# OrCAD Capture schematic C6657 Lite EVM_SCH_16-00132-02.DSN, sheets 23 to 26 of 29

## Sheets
23 PAGE12 : MMC, HYPERLINK CONN: size C; title: MMC, HYPERLINK & 80 CONN
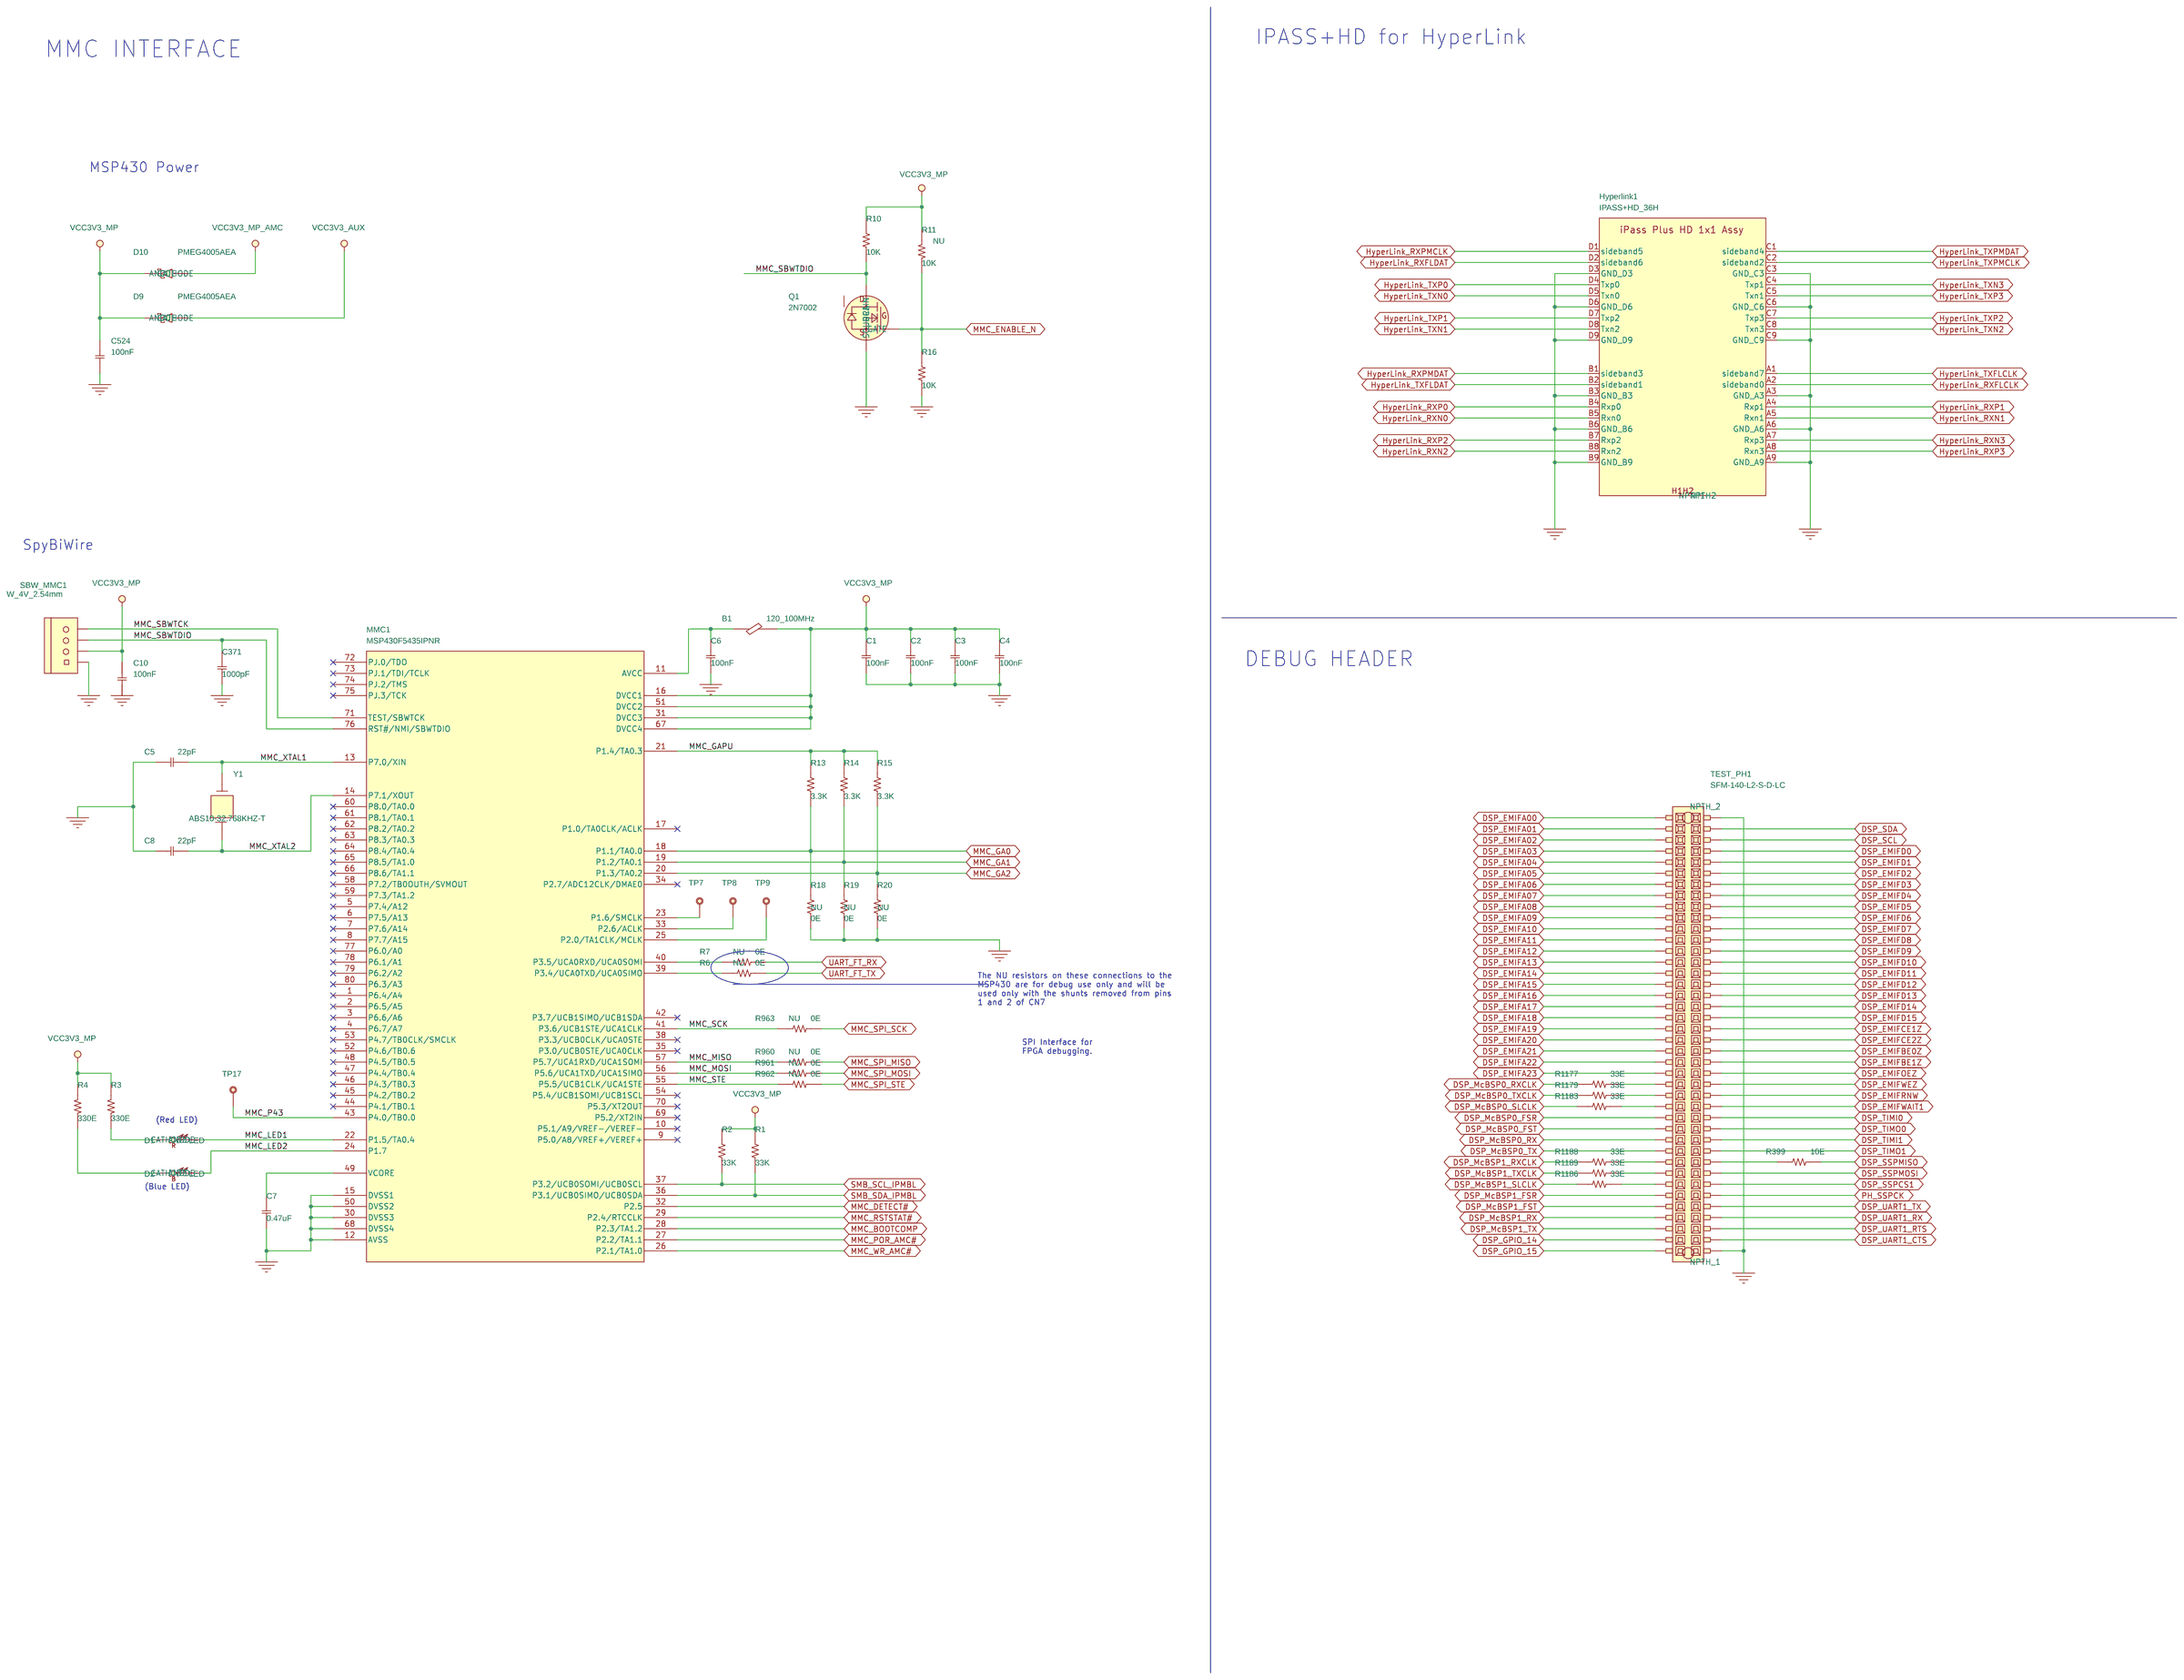
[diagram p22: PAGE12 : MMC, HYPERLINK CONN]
24 PAGE09 : FPGA INTERFACE CTRL: title: CLOCK DIAGRAM
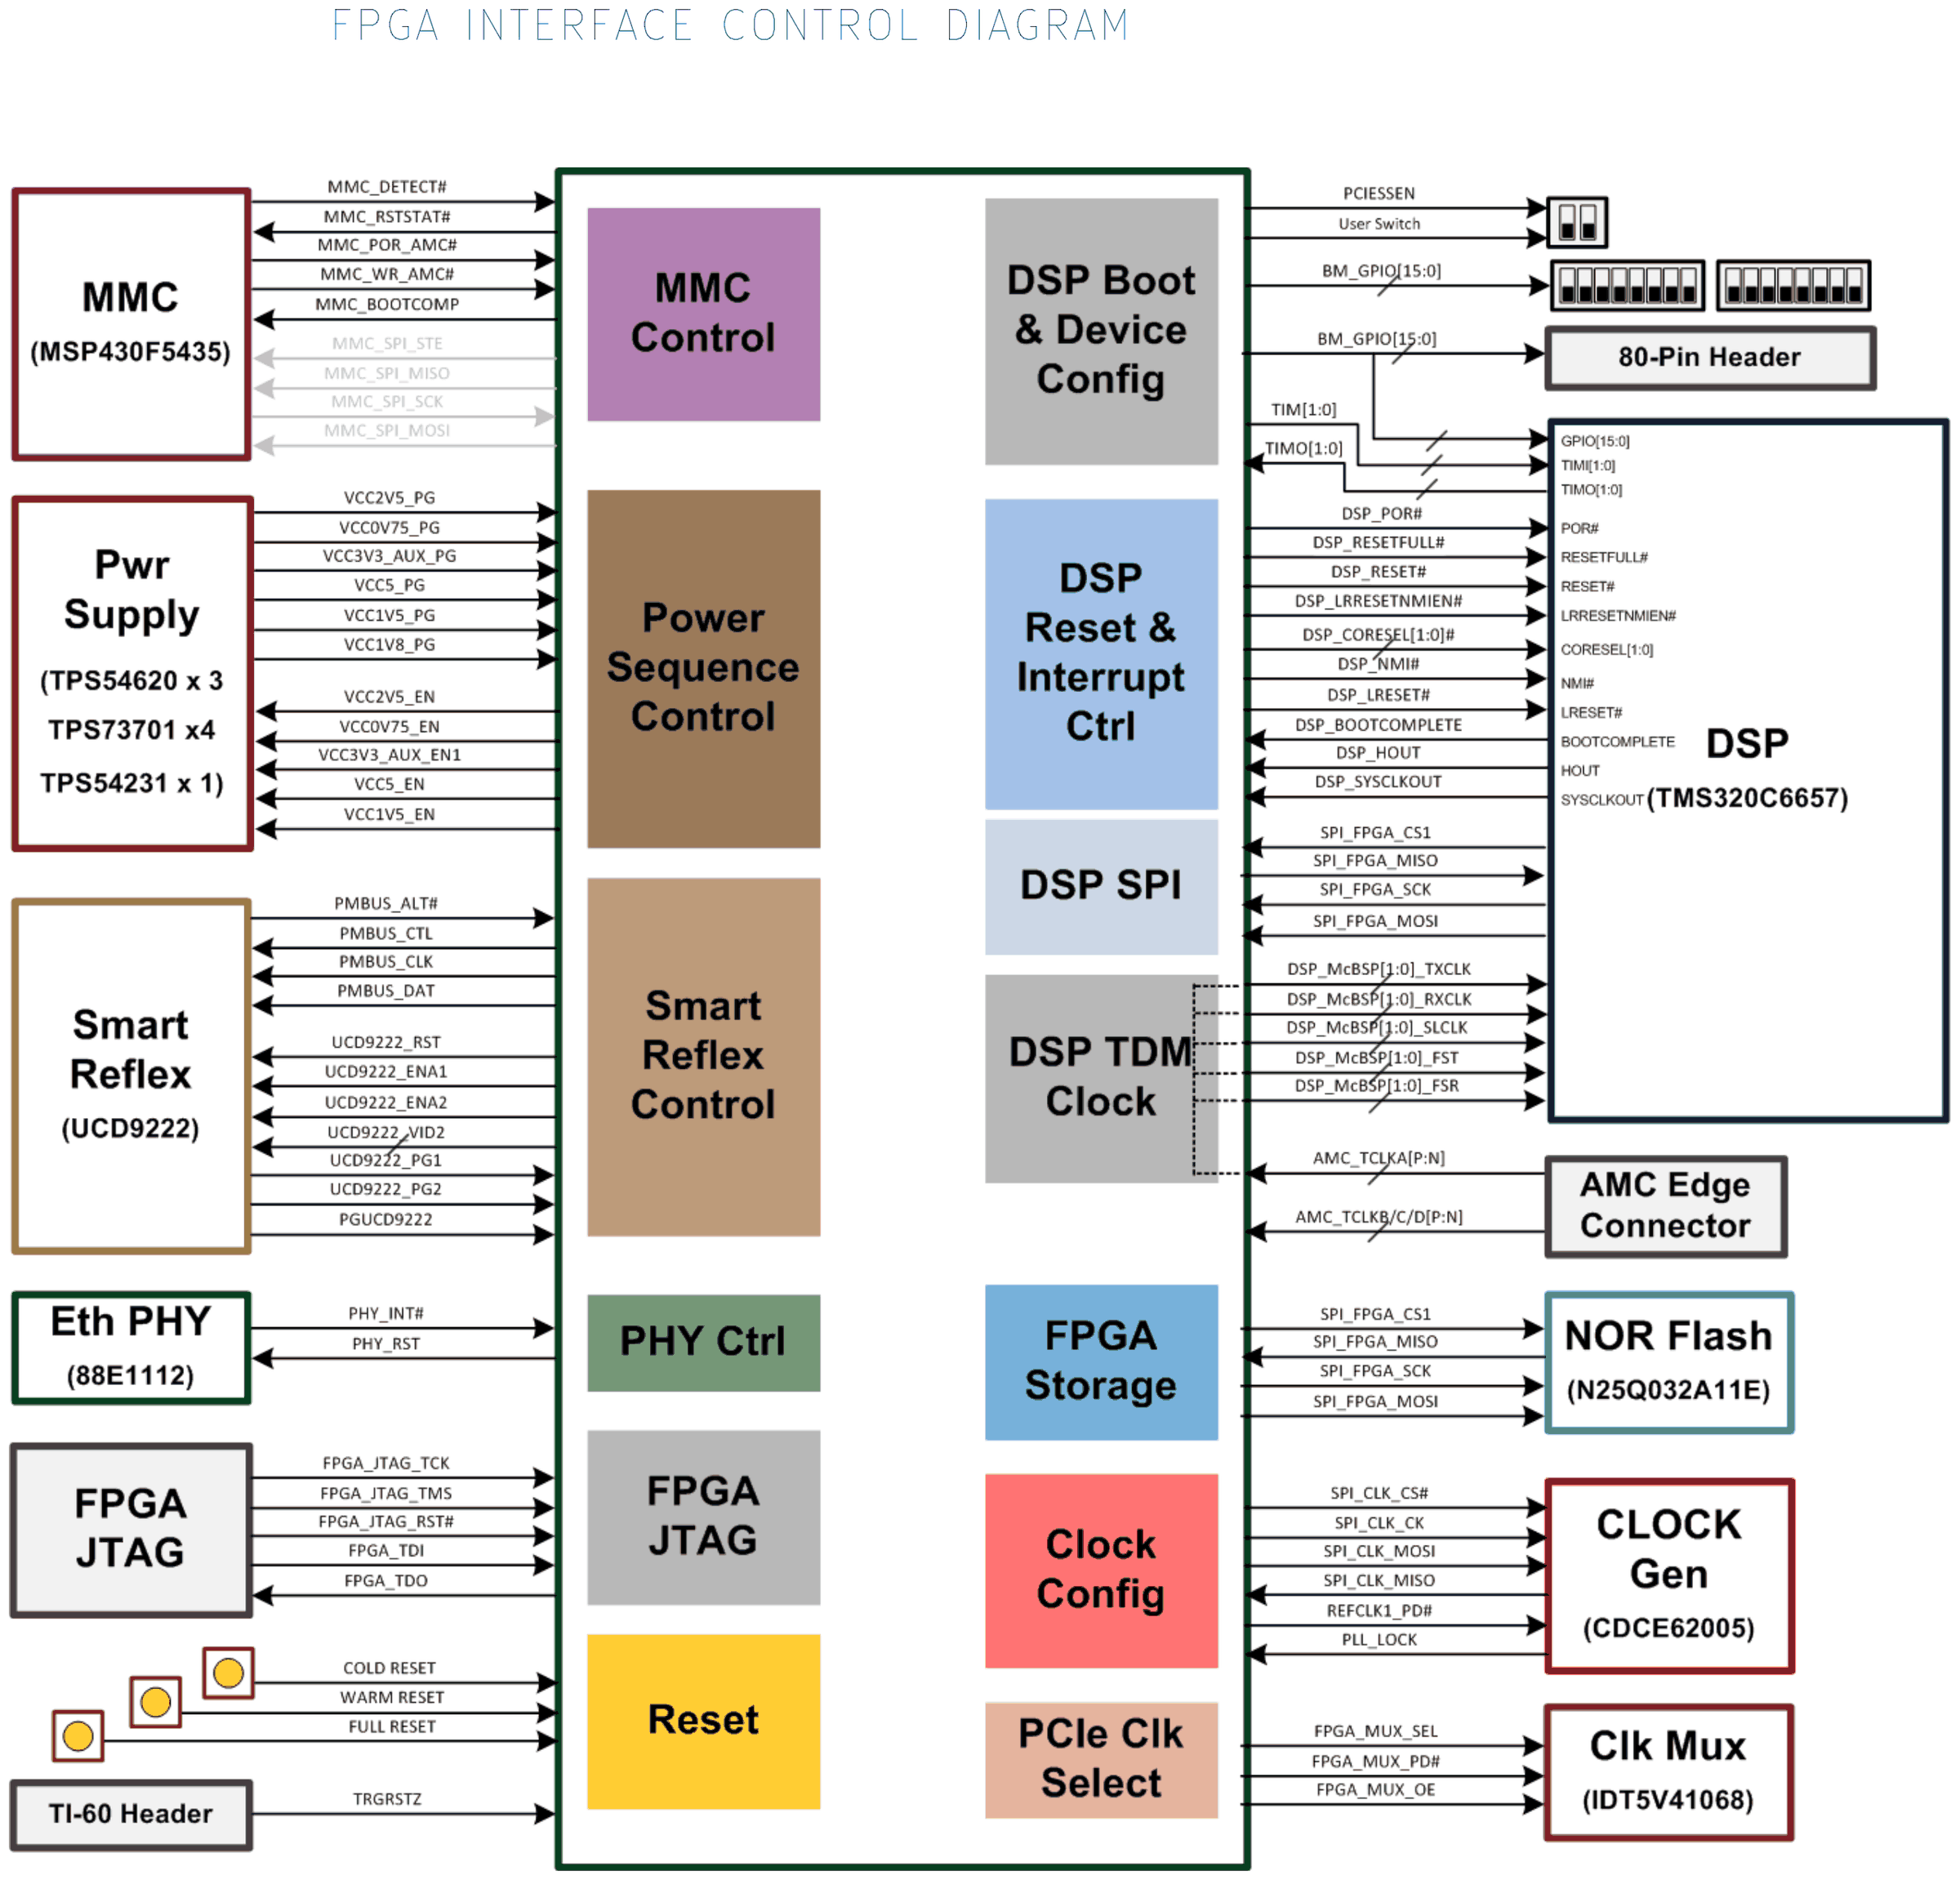
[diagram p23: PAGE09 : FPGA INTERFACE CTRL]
25 PAGE07 : POWER DISTRIBUTION: title: POWER DISTRIBUTION
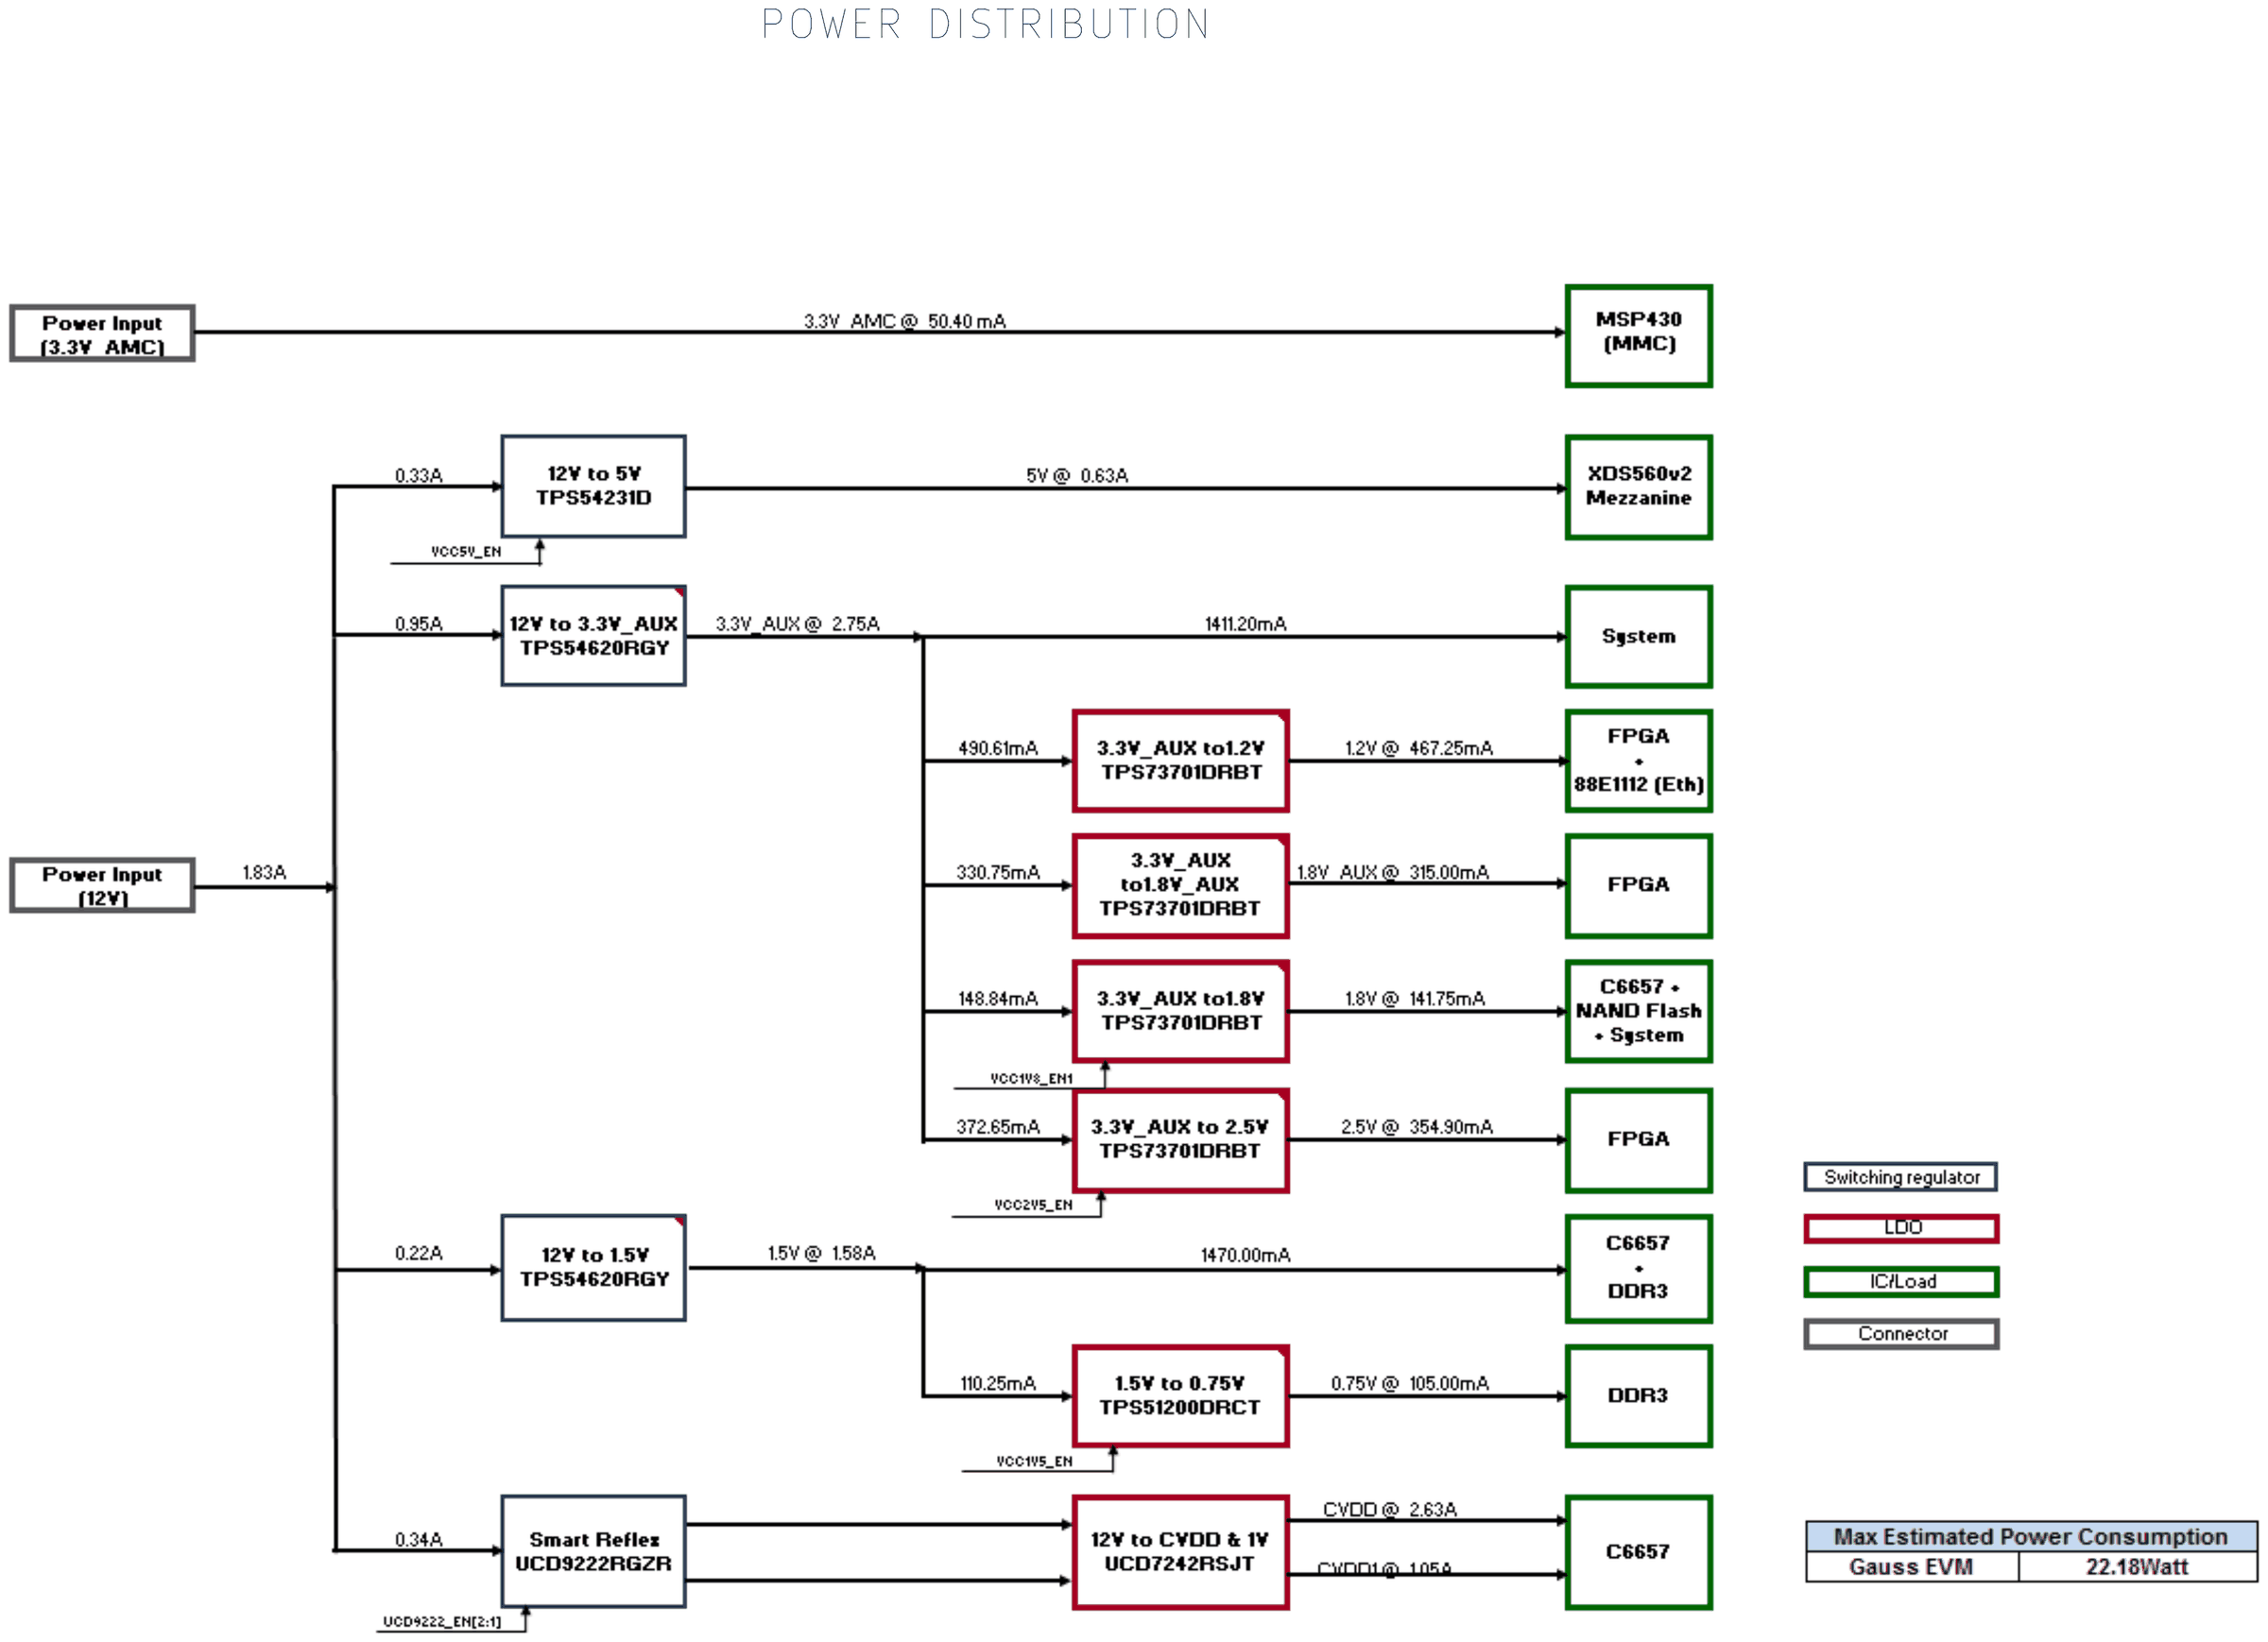
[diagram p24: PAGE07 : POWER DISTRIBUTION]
26 PAGE23 : FPGA-BM & SMART REF: size C; title: FPGA & BM & SMART REFLEX
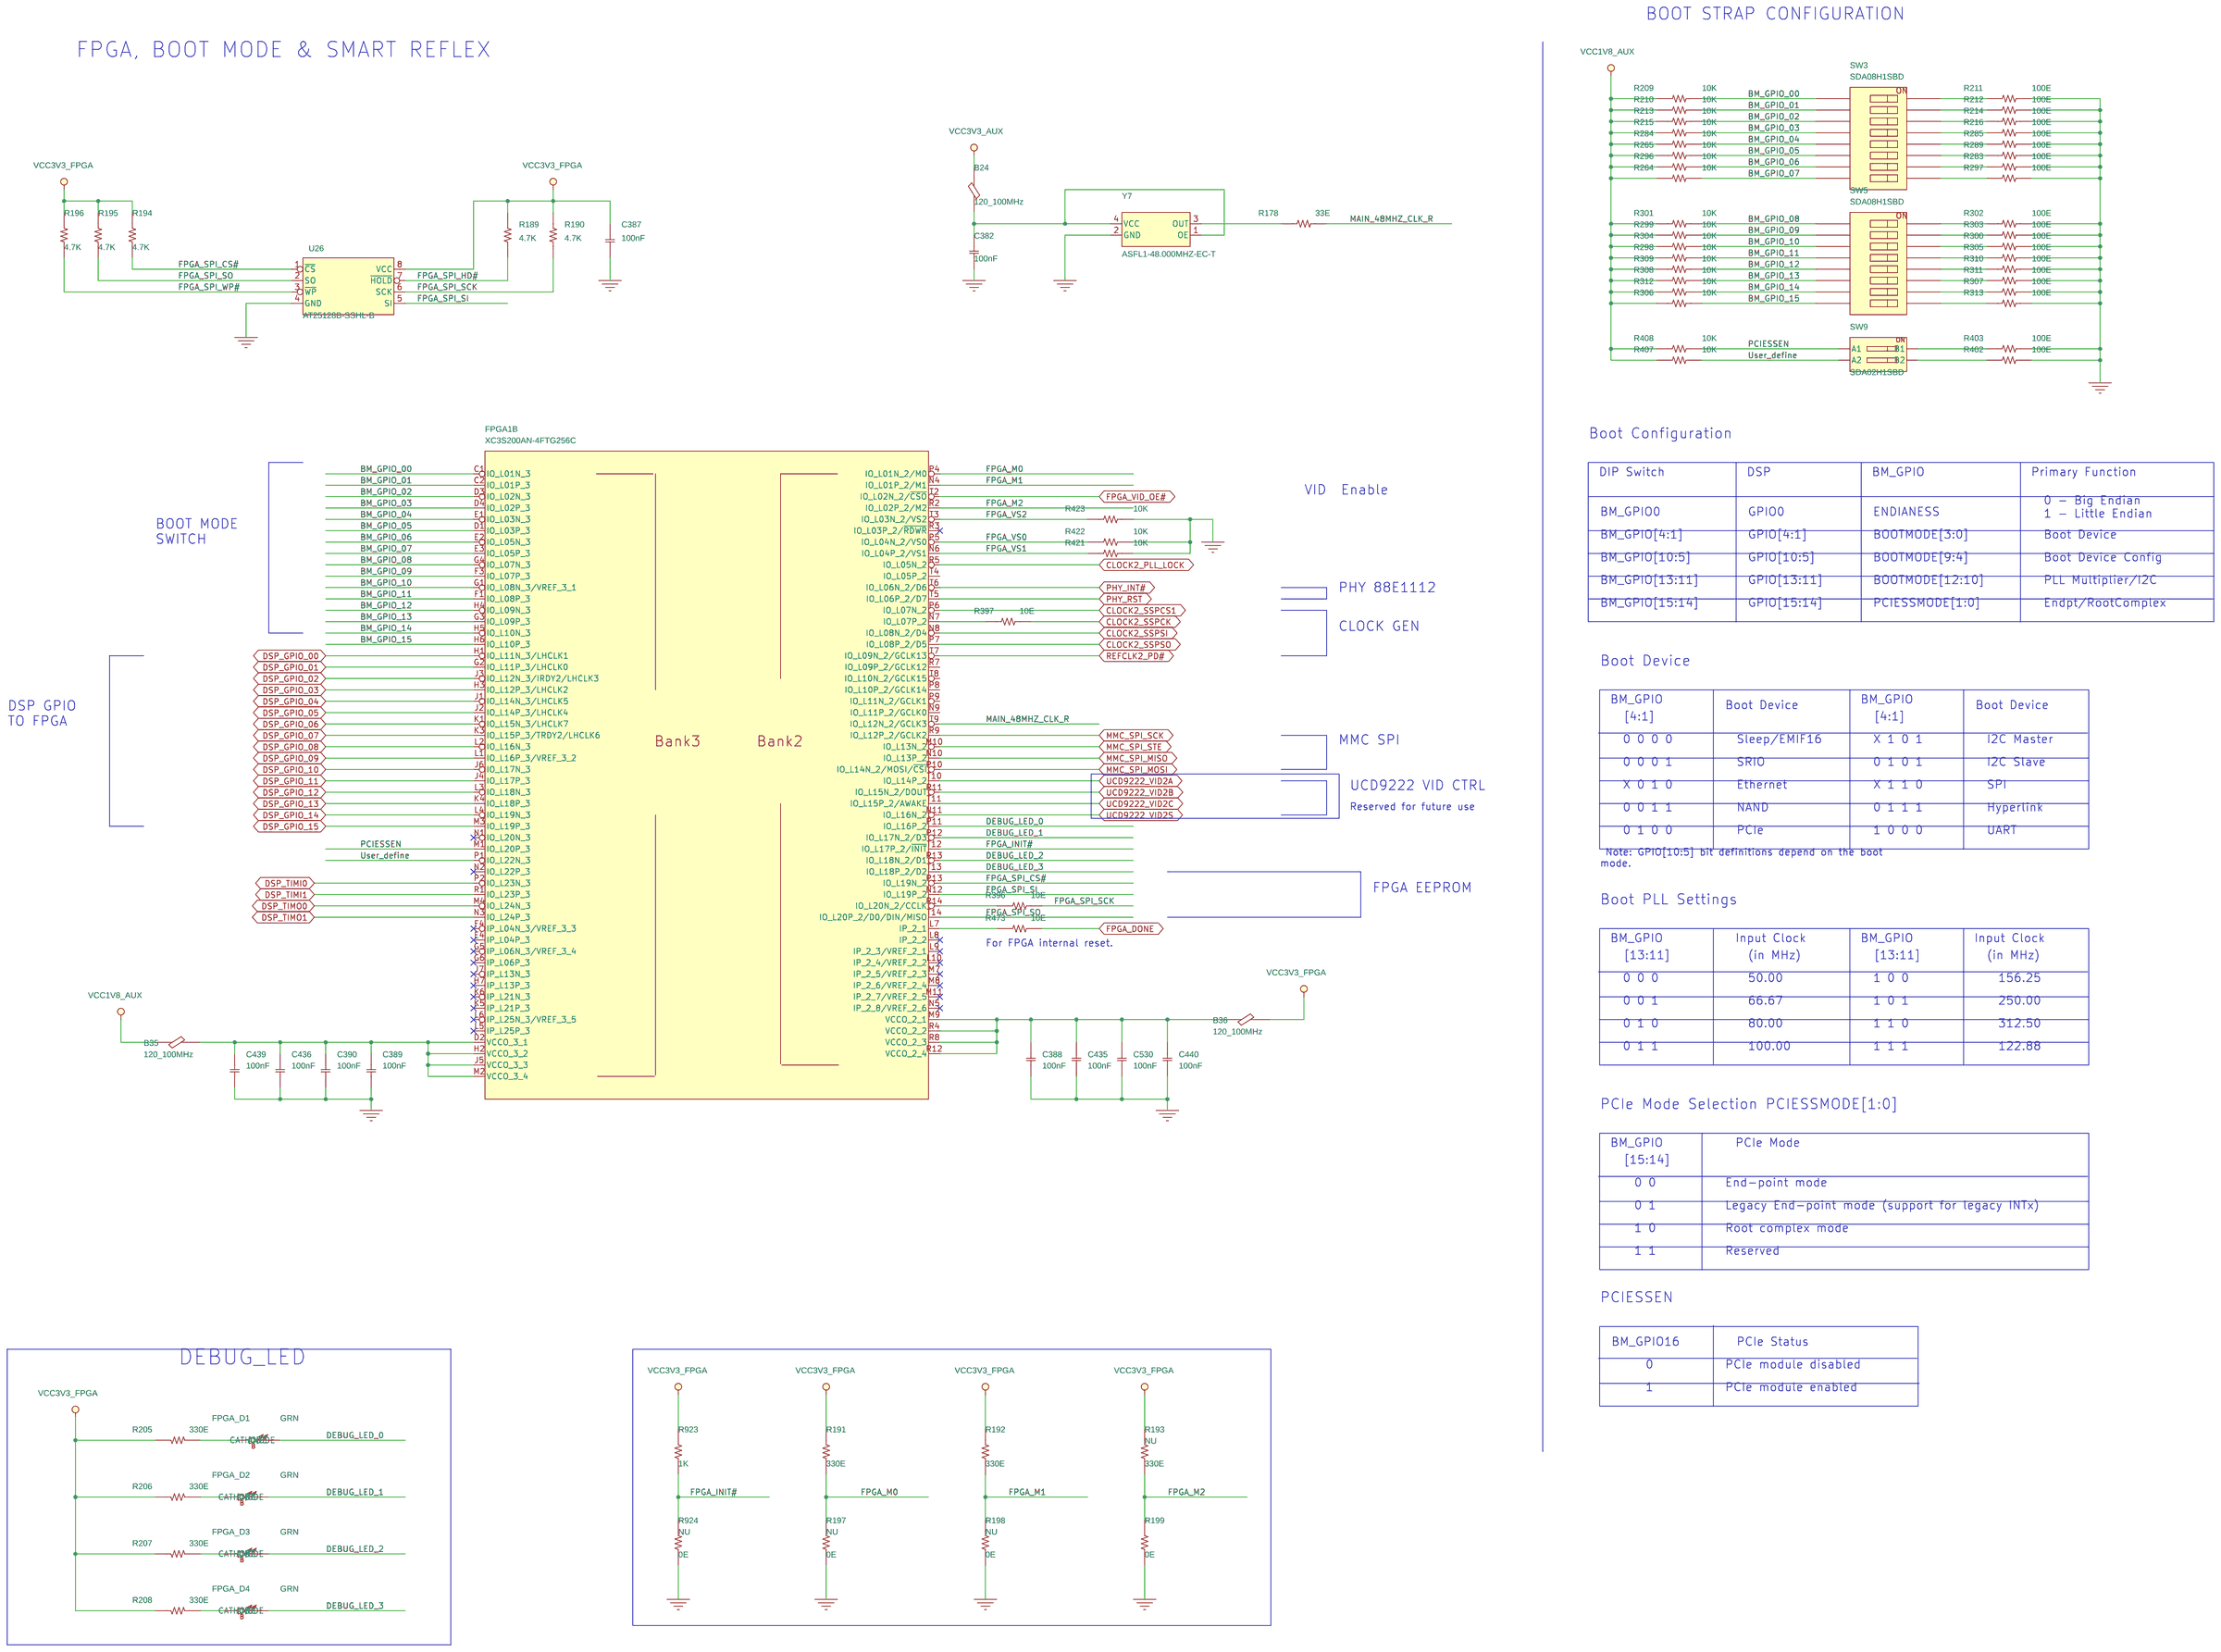
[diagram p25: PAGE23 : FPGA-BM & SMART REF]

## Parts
sheet PAGE12 : MMC, HYPERLINK CONN
B1  120_100MHz  [L0402]
C1  100nF  [C0402]
C2  100nF  [C0402]
C3  100nF  [C0402]
C4  100nF  [C0402]
C5  22pF  [C0402]
C6  100nF  [C0402]
C7  0.47uF  [C0402]
C8  22pF  [C0402]
C10  100nF  [C0402]
C371  1000pF  [C0402]
C524  100nF  [C0402]
D1  LED  [LED_LTST-S270K_RA]
D2  LED  [LED_LTST-S270K_RA]
D9  PMEG4005AEA  [SOD-323]
D10  PMEG4005AEA  [SOD-323]
Hyperlink1  IPASS+HD_36H  [IPASSHD_36P_76867-0011]
MMC1  MSP430F5435IPNR  [QFP_80P_20_551X551]
Q1  2N7002  [SOT-23]
R1  33K  [R0402]
R2  33K  [R0402]
R3  330E  [R0402]
R4  330E  [R0402]
R6  0E  [R0402]
R7  0E  [R0402]
R10  10K  [R0402]
R11  10K  [R0402]
R13  3.3K  [R0402]
R14  3.3K  [R0402]
R15  3.3K  [R0402]
R16  10K  [R0402]
R18  0E  [R0402]
R19  0E  [R0402]
R20  0E  [R0402]
R399  10E  [R0402]
R960  0E  [R0402]
R961  0E  [R0402]
R962  0E  [R0402]
R963  0E  [R0402]
R1177  33E  [R0402]
R1179  33E  [R0402]
R1183  33E  [R0402]
R1186  33E  [R0402]
R1188  33E  [R0402]
R1189  33E  [R0402]
SBW_MMC1  W_4V_2.54mm  [PWR-S4PV]
TEST_PH1  SFM-140-L2-S-D-LC  [HD_40x2P_50_2HOLD_F]
TP7  Test Point  [TP-S40]
TP8  Test Point  [TP-S40]
TP9  Test Point  [TP-S40]
TP17  Test Point  [TP-S40]
Y1  ABS10-32.768KHZ-T  [XTAL_ABS10]
sheet PAGE23 : FPGA-BM & SMART REF
B24  120_100MHz  [L0402]
B35  120_100MHz  [L0603]
B36  120_100MHz  [L0603]
C382  100nF  [C0402]
C387  100nF  [C0402]
C388  100nF  [C0402]
C389  100nF  [C0402]
C390  100nF  [C0402]
C435  100nF  [C0402]
C436  100nF  [C0402]
C439  100nF  [C0402]
C440  100nF  [C0402]
C530  100nF  [C0402]
FPGA1  XC3S200AN-4FTG256C  [BGA_256P_39_669x669_H61]  (sections A,B,C)
FPGA_D1  GRN  [LED_0603]
FPGA_D2  GRN  [LED_0603]
FPGA_D3  GRN  [LED_0603]
FPGA_D4  GRN  [LED_0603]
R178  33E  [R0402]
R189  4.7K  [R0402]
R190  4.7K  [R0402]
R191  330E  [R0402]
R192  330E  [R0402]
R193  330E  [R0402]
R194  4.7K  [R0402]
R195  4.7K  [R0402]
R196  4.7K  [R0402]
R197  0E  [R0402]
R198  0E  [R0402]
R199  0E  [R0402]
R205  330E  [R0402]
R206  330E  [R0402]
R207  330E  [R0402]
R208  330E  [R0402]
R209  10K  [R0402]
R210  10K  [R0402]
R211  100E  [R0402]
R212  100E  [R0402]
R213  10K  [R0402]
R214  100E  [R0402]
R215  10K  [R0402]
R216  100E  [R0402]
R264  10K  [R0402]
R265  10K  [R0402]
R283  100E  [R0402]
R284  10K  [R0402]
R285  100E  [R0402]
R289  100E  [R0402]
R296  10K  [R0402]
R297  100E  [R0402]
R298  10K  [R0402]
R299  10K  [R0402]
R300  100E  [R0402]
R301  10K  [R0402]
R302  100E  [R0402]
R303  100E  [R0402]
R304  10K  [R0402]
R305  100E  [R0402]
R306  10K  [R0402]
R307  100E  [R0402]
R308  10K  [R0402]
R309  10K  [R0402]
R310  100E  [R0402]
R311  100E  [R0402]
R312  10K  [R0402]
R313  100E  [R0402]
R396  10E  [R0402]
R397  10E  [R0402]
R402  100E  [R0402]
R403  100E  [R0402]
R407  10K  [R0402]
R408  10K  [R0402]
R421  10K  [R0402]
R422  10K  [R0402]
R423  10K  [R0402]
R473  10E  [R0402]
R923  1K  [R0402]
R924  0E  [R0402]
SW3  SDA08H1SBD  [SW_SDA08H0SB]
SW5  SDA08H1SBD  [SW_SDA08H0SB]
SW9  SDA02H1SBD  [SW_SDA02H0SB]
U26  AT25128B-SSHL-B  [SOIC_8P_50_193X236]
Y7  ASFL1-48.000MHZ-EC-T  [OSC_535_9259_1]

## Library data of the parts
B1 B24 = 1212_BEAD_0: FERRITE CHIP 120 OHM 500MA 0402; Manufacture Part Number: BLM15AG121SN1D; Mfg: Murata; Mfg Part#: BLM15AG121SN1D; Oper. Temp. Range: -55C to 85C; Package: 0402; ProcessType: SMT; RoHS: Yes; Tolerance: 25%; Vendor: DigiKey; Vendor Part#: 490-1005-1-ND; eI Part#: 04_00075_01
C1-C4 C6 C10 C382 C387-C390 C435 C436 C439 C440 C524 C530 = 11_C_0: CAP CER 0.1UF 10V 10% X5R 0402; Alt Mfg: Murata; Alt Mfg Part#: GRM155R61A104KA01D; Manufacture Part Number: 2238 787 15649||CC0402KRX7R7BB104; Mfg: Yageo; Mfg Part#: CC0402KRX5R6BB104; Oper. Temp. Range: -55C to 85C; Package: 0402; ProcessType: SMT; RoHS: Yes; Tolerance: 10%; Vendor: DigiKey; Vendor Part#: 311-1336-1-ND; eI Part#: 03_00021_02
C5 C8 = 11_C_0: CAP CER 22PF 50V 0402 SMD; Alt Mfg: Yageo; Alt Mfg Part#: CC0402JRNPO9BN220; Mfg: Panasonic - ECG; Mfg Part#: ECJ-0EC1H220J; Oper. Temp. Range: -55C to 125C; Package: 0402; ProcessType: SMT; RoHS: Yes; Tolerance: 5%; Vendor: DigiKey; Vendor Part#: PCC220CQCT-ND; eI Part#: 03_00204_02
C7 = 11_C_0: CAP CER 0.47UF 10V 10% X5R 0402; Alt Mfg: Murata; Alt Mfg Part#: GRM155R61A474KE15D; Mfg: TDK Corp; Mfg Part#: C1005X5R1A474K; Package: 0402; ProcessType: SMT; RoHS: Yes; Tolerance: 10%; Vendor: DigiKey; Vendor Part#: 445-4989-1-ND; eI Part#: 03_00468_02
C371 = 11_C_0: CAP CER 1000PF 25V X7R 0402; Mfg: Johnson Dielectrics Inc; Mfg Part#: 250R07W102KV4T; Oper. Temp. Range: -55C to 125C; Package: 0402; ProcessType: SMT; RoHS: Yes; Tolerance: 10%; Vendor: DigiKey; Vendor Part#: 709-1131-1-ND; eI Part#: 03_00289_01
D1 = 130_LED_LED-0603_R_0: LED SUPR RED CLR 0603 RT ANG SMD; Mfg: Lite-On Inc; Mfg Part#: LTST-S270KRKT; Oper. Temp. Range: -55 to +85C; Package: 0603; ProcessType: SMT; RoHS: Yes; Vendor: DigiKey; Vendor Part#: 160-1479-1-ND; eI Part#: 06_00071_01
D2 = 130_LED_2P_B_0: LED 468NM RA BLUE CLEAR 0603 SMD; Mfg: Lite-On Inc; Mfg Part#: LTST-S270TBKT; Oper. Temp. Range: -55 to +85C; Package: 0603; ProcessType: SMT; Remark: Alt net part is with 0603 FP; RoHS: Yes; Vendor: DigiKey; Vendor Part#: 160-1650-1-ND; eI Part#: 06_00224_01
D9 D10 = 130_Schottky_SOD-323: SCHOTTKY RECT 40V 0.5A SOD323; Manufacture Part Number: PMEG4005AEA,115; Mfg: NXP Semiconductors; Mfg Part#: PMEG4005AEA,115; Oper. Temp. Range: -55 to +125C; ProcessType: SMT; RoHS: Yes; Vendor: DigiKey; Vendor Part#: 568-6521-1-ND; eI Part#: 06_0030_01
Hyperlink1 = 1654_IPASS_36P_76867-0011_0: CONN HD INTERNAL CABLE 1X1 GOLD; Manufacture Part Number: 76867-0011; Mfg: Molex; Mfg Part#: 0768670011; Package: IPASS+HD36P; ProcessType: DIP; RoHS: Yes; Vendor: DigiKey; Vendor Part#: 0768670011-ND; eI Part#: 09_00651_01
MMC1 = MSP430F5435IPN_0: IC MCU 16BIT 192K FLASH 80-LQFP; Mfg: Texas Instruments; Package: 80-LQFP; Vendor: DigiKey; Vendor Part#: 296-23764-1-ND; eI Part#: 01_00400_01
Q1 = 131_N_MOS_SOT-23_1: MOSFET N-CH 60V 300MA SOT-23; Mfg: NXP Semiconductors; Mfg Part#: 2N7002,215; ProcessType: SMT; RoHS: Yes; Vendor: DigiKey; Vendor Part#: 568-1369-2-ND; eI Part#: 07_00015_02
R1 R2 = 10_R_0: RES 33K OHM 1/10W 5% 0402 SMD; Alt Mfg: Yageo; Alt Mfg Part#: RC0402JR-0733KL; Mfg: Panasonic - ECG; Mfg Part#: ERJ-2GEJ333X; Oper. Temp. Range: -55C to 125C; Package: 0402; ProcessType: SMT; Remark: Alt part is 1/16W; RoHS: Yes; Tolerance: 5%; Vendor: DigiKey; Vendor Part#: P33KJCT-ND; eI Part#: 02_00356_01
R3 R4 = 10_R_0: RES 330 OHM 1/10W 5% 0402 SMD; Alt Mfg: Yageo; Alt Mfg Part#: RC0402JR-07330RL; Mfg: Panasonic - ECG; Mfg Part#: ERJ-2GEJ331X; Package: 0402; ProcessType: SMT; Remark: Alt part is 1/16W; RoHS: Yes; Tolerance: 5%; Vendor: DigiKey; Vendor Part#: P330JCT-ND; eI Part#: 02_00032_01
R6 R7 R18-R20 R197 R198 R924 R960-R963 = 10_R_0: RES ZERO OHM 1/10W 5% 0402 SMD; Alt Mfg: Yageo; Alt Mfg Part#: RC0402JR-070RL; Mfg: Panasonic - ECG; Mfg Part#: ERJ-2GE0R00X; Mounting Status: NU; Mounting_Status: NU; Oper. Temp. Range: -55C to 125C; Package: 0402; ProcessType: SMT; Remark: Alt part is 1/16W; RoHS: Yes; Tolerance: 5%; Vendor: DigiKey; Vendor Part#: P0.0JCT-ND; eI Part#: 02_00019_01
R10 R16 R209 R210 R213 R215 R264 R265 R284 R296 R298 R299 R301 R304 R306 R308 R309 R312 R407 R408 R421-R423 = 10_R_0: RES 10.0K OHM 1/10W 1% 0402 SMD; Alt Mfg: Yageo; Alt Mfg Part#: RC0402FR-0710KL; Manufacture Part Number: 0402WGF1002TCE||RM04FTN1002; Mfg: Panasonic - ECG; Mfg Part#: ERJ-2RKF1002X; Oper. Temp. Range: -55C ~ 125C; Package: 0402; ProcessType: SMT; Remark: Alt part is 1/16W; RoHS: Yes; Tolerance: 1%; Vendor: DigiKey; Vendor Part#: P10.0KLCT-ND; eI Part#: 02_00027_01
R11 = 10_R_0: RES 10.0K OHM 1/10W 1% 0402 SMD; Alt Mfg: Yageo; Alt Mfg Part#: RC0402FR-0710KL; Manufacture Part Number: 0402WGF1002TCE||RM04FTN1002; Mfg: Panasonic - ECG; Mfg Part#: ERJ-2RKF1002X; Mounting Status: NU; Mounting_Status: NU; Oper. Temp. Range: -55C ~ 125C; Package: 0402; ProcessType: SMT; Remark: Alt part is 1/16W; RoHS: Yes; Tolerance: 1%; Vendor: DigiKey; Vendor Part#: P10.0KLCT-ND; eI Part#: 02_00027_01
R13-R15 = 10_R_0: RES 3.3K OHM 1/10W 5% 0402 SMD; Alt Mfg: Yageo; Alt Mfg Part#: RC0402JR-073K3L; Mfg: Panasonic - ECG; Mfg Part#: ERJ-2GEJ332X; Oper. Temp. Range: -55C to 125C; Package: 0402; ProcessType: SMT; Remark: Alt part is 1/16W; RoHS: Yes; Tolerance: 5%; Vendor: DigiKey; Vendor Part#: P3.3KJCT-ND; eI Part#: 02_00355_01
R396 R397 R399 R473 = 10_R_0: RES 10.0 OHM 1/10W 1% 0402 SMD; Manufacture Part Number: 0402WGJ0100TCE||RC0402JR-0710RL||RM04JTN100; Mfg: Panasonic - ECG; Mfg Part#: ERJ-2RKF10R0X; Oper. Temp. Range: -55C to 125C; Package: 0402; ProcessType: SMT; RoHS: Yes; Tolerance: 1%; Vendor: DigiKey; Vendor Part#: P10.0LCT-ND; eI Part#: 02_00060_01
R178 R1177 R1179 R1183 R1186 R1188 R1189 = 10_R_0: RES 33.0 OHM 1/10W 1% 0402 SMD; Alt Mfg: Yageo; Alt Mfg Part#: RC0402FR-0733RL; Manufacture Part Number: 0402WGJ0330TCE||232270570339L||RC0402JR-0733RL||RM04JTN330; Mfg: Panasonic - ECG; Mfg Part#: ERJ-2RKF33R0X; Oper. Temp. Range: -55C to 125C; Package: 0402; ProcessType: SMT; Remark: Alt part is 1/16W; RoHS: Yes; Tolerance: 1%; Vendor: DigiKey; Vendor Part#: P33.0LCT-ND; eI Part#: 02_00018_05
SBW_MMC1 = 1655_PWR-S4PV_0: CONN HEADER VERT 4POS .100 TIN; Manufacture Part Number: 2542A-WS-4; Mfg: TE Connectivity; Mfg Part#: 640454-4; Package: WAFER4P-2.54; ProcessType: DIP; RoHS: Yes; Vendor: DigiKey; Vendor Part#: A19431-ND; eI Part#: 09_00659_01
TEST_PH1 = 1653_HD_40X2P_F_L1_0: CONN HEADER 80POS .100" SMD TIN; Manufacture Part Number: 22L8742-80M0PB-01G-A; Mfg: Samtec; Oper. Temp. Range: -55C to 125C; Package: PH(F)40x2P-S1.27; ProcessType: SMT; RoHS: Yes; Vendor: Samtec; eI Part#: 09_00145_01
TP7-TP9 TP17 = 00_TP-S40_0: TEST PAD TP-S40; Mfg: --NA--; Mfg Part#: --NA--; Oper. Temp. Range: --NA--; Package: --NA--; ProcessType: SMT; RoHS: Yes; Vendor: --NA--; Vendor Part#: --NA--; eI Part#: --NA--
Y1 = Crystal-2pin: CRYSTAL 32.768KHZ 12.5PF SMD; Mfg: Abracon Corporation; Oper. Temp. Range: -40C to 85C; Package: 4.9mm x 1.8mm; RoHS: Yes; Specifications: CRYSTAL 32.768KHZ 12.5PF SMD; Vendor: DigiKey; Vendor Part#: 535-9536-1-ND; eI Part#: 08_00005_02
B35 B36 = 1212_BEAD_0: FERRITE CHIP 120 OHM 2000MA 0603; Manufacture Part Number: BLM18PG121SN1; Mfg: Murata; Mfg Part#: BLM18PG121SN1D; Oper. Temp. Range: -55C to 85C; Package: 0603; ProcessType: SMT; RoHS: Yes; Tolerance: 25%; Vendor: DigiKey; Vendor Part#: 490-1037-1-ND; eI Part#: 04_00023_01
FPGA1 = XC3S200AN-4FTG256C: IC SPARTAN-3AN FPGA 200K 256FTBG; Mfg: Xilinx Inc; Oper. Temp. Range: 0°C ~ 85°C; Package: FTBGA256; ProcessType: SMT; RoHS: Yes; Vendor: DigiKey; Vendor Part#: 122-1553-ND; eI Part#: 01_00848_01
FPGA_D1-FPGA_D4 = 130_LED_2P_B_0: LED 565NM GRN DIFF 0603 SMD; Manufacture Part Number: 19-215SUBC/S280/TR8; Mfg: Lumex Opto/Components Inc; Mfg Part#: SML-LX0603GW-TR; Package: 0603; ProcessType: SMT; RoHS: Yes; Vendor: DigiKey; Vendor Part#: 67-1549-1-ND; eI Part#: 06_00007_01
R189 R190 R194-R196 = 10_R_0: RES 4.7K OHM 1/10W 5% 0402 SMD; Alt Mfg: Yageo; Alt Mfg Part#: RC0402JR-074K7L; Manufacture Part Number: 0402WGJ0472TCE||RC0402JR-074K7L||RM04JTN472; Mfg: Panasonic - ECG; Mfg Part#: ERJ-2GEJ472X; Oper. Temp. Range: -55C to 125C; Package: 0402; ProcessType: SMT; Remark: Alt part is 1/16W; RoHS: Yes; Tolerance: 5%; Vendor: DigiKey; Vendor Part#: P4.7KJCT-ND; eI Part#: 02_00023_01
R191 R192 R205-R208 = 10_R_0: RES 330 OHM 1/10W 5% 0402 SMD; Alt Mfg: Yageo; Alt Mfg Part#: RC0402JR-07330RL; Manufacture Part Number: 0402WGJ0331TCE||RM04JTN331; Mfg: Panasonic - ECG; Mfg Part#: ERJ-2GEJ331X; Package: 0402; ProcessType: SMT; Remark: Alt part is 1/16W; RoHS: Yes; Tolerance: 5%; Vendor: DigiKey; Vendor Part#: P330JCT-ND; eI Part#: 02_00032_01
R193 = 10_R_0: RES 330 OHM 1/10W 5% 0402 SMD; Alt Mfg: Yageo; Alt Mfg Part#: RC0402JR-07330RL; Manufacture Part Number: 0402WGJ0331TCE||RM04JTN331; Mfg: Panasonic - ECG; Mfg Part#: ERJ-2GEJ331X; Mounting Status: NU; Mounting_Status: NU; Package: 0402; ProcessType: SMT; Remark: Alt part is 1/16W; RoHS: Yes; Tolerance: 5%; Vendor: DigiKey; Vendor Part#: P330JCT-ND; eI Part#: 02_00032_01
R199 = 10_R_0: RES ZERO OHM 1/10W 5% 0402 SMD; Alt Mfg: Yageo; Alt Mfg Part#: RC0402JR-070RL; Mfg: Panasonic - ECG; Mfg Part#: ERJ-2GE0R00X; Oper. Temp. Range: -55C to 125C; Package: 0402; ProcessType: SMT; Remark: Alt part is 1/16W; RoHS: Yes; Tolerance: 5%; Vendor: DigiKey; Vendor Part#: P0.0JCT-ND; eI Part#: 02_00019_01
R211 R212 R214 R216 R283 R285 R289 R297 R300 R302 R303 R305 R307 R310 R311 R313 R402 R403 = 10_R_0: RES 100 OHM 1/10W 1% 0402 SMD; Manufacture Part Number: 0402WGF1000TCE||232270671001L||RM04FTN1000; Mfg: Panasonic - ECG; Mfg Part#: ERJ-2RKF1000X; Oper. Temp. Range: -55C to 125C; Package: 0402; ProcessType: SMT; RoHS: Yes; Tolerance: 1%; Vendor: DigiKey; Vendor Part#: P100LCT-ND; eI Part#: 02_00043_02
R923 = 10_R_0: RES 1.00K OHM 1/10W 1% 0402 SMD; Alt Mfg: Yageo; Alt Mfg Part#: RC0402FR-071KL; Manufacture Part Number: 0402WGF1001TCE||RM04FTN1001; Mfg: Panasonic - ECG; Mfg Part#: ERJ-2RKF1001X; Oper. Temp. Range: -55C to 125C; Package: 0402; ProcessType: SMT; RoHS: Yes; Tolerance: 1%; Vendor: DigiKey; Vendor Part#: P1.00KLCT-ND; eI Part#: 02_00045_01
SW3 SW5 = DIP_Switch_-_8: SWITCH DIP TOP SLIDE 8POS SMD; Mfg: C & K Components; Oper. Temp. Range: -40C to 85C; RoHS: Yes; Specifications: SWITCH DIP TOP SLIDE 8POS SMD; Vendor: DigiKey; Vendor Part#: CKN6092-ND; eI Part#: 11_00019_01
SW9 = 160_SW_4P_ESD102EZ_0: SWITCH DIP TOP SLIDE 2POS SMD; Manufacture Part Number: ESD102EZ; Mfg: C & K Components; Oper. Temp. Range: -40C to 85C; ProcessType: SMT; RoHS: Yes; Vendor: DigiKey; Vendor Part#: CKN6056-ND; eI Part#: 11_00058_01
U26 = 141_ATMEL_AT25128B-SSHL-B: IC EEPROM 128KBIT 20MHZ 8SOIC; Mfg: Atmel; Oper. Temp. Range: -40°C ~ 85°C; Package: SOIC8; ProcessType: SMT; RoHS: Yes; Vendor: DigiKey; Vendor Part#: AT25128B-SSHL-B-ND; eI Part#: 01_00840_01
Y7 = 1233_OSC_4P_0: OSCILLATOR 48.0000 MHZ 3.3V SMD; Manufacture Part Number: 7W48000032; Mfg: Abracon Corporation; Oper. Temp. Range: -20°C ~ 70°C; Package: 5.00mm x 3.20mm; ProcessType: SMT; RoHS: Yes; Tolerance: 50ppm; Vendor: DigiKey; Vendor Part#: 300-8263-1-ND; eI Part#: 08_00128_01

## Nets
GND: C1.2 C2.2 C3.2 C4.2 C5.2 C6.1 C7.1 C8.2 C10.1 C371.1 C382.1 C387.1 C388.1 C389.1 C390.1 C435.1 C436.1 C439.1 C440.1 C524.2 C530.1 Hyperlink1.A3(GND) Hyperlink1.A6(GND) Hyperlink1.A9(GND) Hyperlink1.B3(GND) Hyperlink1.B6(GND) Hyperlink1.B9(GND) Hyperlink1.C3(GND) Hyperlink1.C6(GND) Hyperlink1.C9(GND) Hyperlink1.D3(GND) Hyperlink1.D6(GND) Hyperlink1.D9(GND) MMC1.12(AVSS) MMC1.15(DVSS1) MMC1.30(DVSS3) MMC1.50(DVSS2) MMC1.68(DVSS4) Q1.2(SOURCE) R16.2 R18.2 R19.2 R20.2 R197.2 R198.2 R199.2 R211.1 R212.1 R214.1 R216.1 R283.1 R285.1 R289.1 R297.1 R300.1 R302.1 R303.1 R305.1 R307.1 R310.1 R311.1 R313.1 R402.1 R403.1 R421.1 R422.1 R423.1 R924.2 SBW_MMC1.1 TEST_PH1.1 TEST_PH1.79 U26.4(GND) Y7.2(GND) ; also on sheet 4 5 6 7 8 9 12 13 14 15 16 19 20 27 28 29
VCC1V8_AUX: B35.1 R209.2 R210.2 R213.2 R215.2 R264.2 R265.2 R284.2 R296.2 R298.2 R299.2 R301.2 R304.2 R306.2 R308.2 R309.2 R312.2 R407.2 R408.2 ; also on sheet 6 12 15 29
VCC3V3_AUX: B24.2 D9.2(ANODE) ; also on sheet 4 6 12 13 14 15 16 20 27 28 29
VCC3V3_FPGA: B36.2 C387.2 R189.2 R190.2 R191.1 R192.1 R193.1 R194.1 R195.1 R196.1 R205.2 R206.2 R207.2 R208.2 R923.1 U26.8(VCC) ; also on sheet 29
VCC3V3_MP: B1.2 C1.1 C2.1 C3.1 C4.1 C10.2 C524.1 D9.1(CATHODE) D10.1(CATHODE) MMC1.16(DVCC1) MMC1.31(DVCC3) MMC1.51(DVCC2) MMC1.67(DVCC4) R1.2 R2.2 R3.1 R4.1 R10.1 R11.2 SBW_MMC1.2
VCC3V3_MP_AMC: D10.2(ANODE) ; also on sheet 12
BM_GPIO_00: FPGA1.C1(IO_L01N_3) R209.1 SW3.1
BM_GPIO_01: FPGA1.C2(IO_L01P_3) R210.1 SW3.2
BM_GPIO_02: FPGA1.D3(IO_L02N_3) R213.1 SW3.3
BM_GPIO_03: FPGA1.D4(IO_L02P_3) R215.1 SW3.4
BM_GPIO_04: FPGA1.E1(IO_L03N_3) R284.1 SW3.5
BM_GPIO_05: FPGA1.D1(IO_L03P_3) R265.1 SW3.6
BM_GPIO_06: FPGA1.E2(IO_L05N_3) R296.1 SW3.7
BM_GPIO_07: FPGA1.E3(IO_L05P_3) R264.1 SW3.8
BM_GPIO_08: FPGA1.G4(IO_L07N_3) R301.1 SW5.1
BM_GPIO_09: FPGA1.F3(IO_L07P_3) R299.1 SW5.2
BM_GPIO_10: FPGA1.G1(IO_L08N_3/VREF_3_1) R304.1 SW5.3
BM_GPIO_11: FPGA1.F1(IO_L08P_3) R298.1 SW5.4
BM_GPIO_12: FPGA1.H4(IO_L09N_3) R309.1 SW5.5
BM_GPIO_13: FPGA1.G3(IO_L09P_3) R308.1 SW5.6
BM_GPIO_14: FPGA1.H5(IO_L10N_3) R312.1 SW5.7
BM_GPIO_15: FPGA1.H6(IO_L10P_3) R306.1 SW5.8
CLOCK2_PLL_LOCK: FPGA1.R5(IO_L05N_2) ; also on sheet 20
CLOCK2_SSPCK: R397.2 ; also on sheet 20
CLOCK2_SSPCS1: FPGA1.P6(IO_L07N_2) ; also on sheet 20
CLOCK2_SSPSI: FPGA1.N8(IO_L08N_2/D4) ; also on sheet 20
CLOCK2_SSPSO: FPGA1.P7(IO_L08P_2/D5) ; also on sheet 20
DEBUG_LED_0: FPGA1.P11(IO_L16P_2) FPGA_D1.2(CATHODE)
DEBUG_LED_1: FPGA1.P12(IO_L17N_2/D3) FPGA_D2.2(CATHODE)
DEBUG_LED_2: FPGA1.R13(IO_L18N_2/D1) FPGA_D3.2(CATHODE)
DEBUG_LED_3: FPGA1.T13(IO_L18P_2/D2) FPGA_D4.2(CATHODE)
DSP_EMIFA00: TEST_PH1.2 ; also on sheet 16
DSP_EMIFA01: TEST_PH1.4 ; also on sheet 16
DSP_EMIFA02: TEST_PH1.6 ; also on sheet 16
DSP_EMIFA03: TEST_PH1.8 ; also on sheet 16
DSP_EMIFA04: TEST_PH1.10 ; also on sheet 16
DSP_EMIFA05: TEST_PH1.12 ; also on sheet 16
DSP_EMIFA06: TEST_PH1.14 ; also on sheet 16
DSP_EMIFA07: TEST_PH1.16 ; also on sheet 16
DSP_EMIFA08: TEST_PH1.18 ; also on sheet 16
DSP_EMIFA09: TEST_PH1.20 ; also on sheet 16
DSP_EMIFA10: TEST_PH1.22 ; also on sheet 16
DSP_EMIFA11: TEST_PH1.24 ; also on sheet 16
DSP_EMIFA12: TEST_PH1.26 ; also on sheet 16
DSP_EMIFA13: TEST_PH1.28 ; also on sheet 16
DSP_EMIFA14: TEST_PH1.30 ; also on sheet 16
DSP_EMIFA15: TEST_PH1.32 ; also on sheet 16
DSP_EMIFA16: TEST_PH1.34 ; also on sheet 16
DSP_EMIFA17: TEST_PH1.36 ; also on sheet 16
DSP_EMIFA18: TEST_PH1.38 ; also on sheet 16
DSP_EMIFA19: TEST_PH1.40 ; also on sheet 16
DSP_EMIFA20: TEST_PH1.42 ; also on sheet 16
DSP_EMIFA21: TEST_PH1.44 ; also on sheet 16
DSP_EMIFA22: TEST_PH1.46 ; also on sheet 16
DSP_EMIFA23: TEST_PH1.48 ; also on sheet 16
DSP_EMIFBE0Z: TEST_PH1.43 ; also on sheet 16
DSP_EMIFBE1Z: TEST_PH1.45 ; also on sheet 16
DSP_EMIFCE1Z: TEST_PH1.39 ; also on sheet 16
DSP_EMIFCE2Z: TEST_PH1.41 ; also on sheet 16
DSP_EMIFD0: TEST_PH1.7 ; also on sheet 16
DSP_EMIFD1: TEST_PH1.9 ; also on sheet 16
DSP_EMIFD2: TEST_PH1.11 ; also on sheet 16
DSP_EMIFD3: TEST_PH1.13 ; also on sheet 16
DSP_EMIFD4: TEST_PH1.15 ; also on sheet 16
DSP_EMIFD5: TEST_PH1.17 ; also on sheet 16
DSP_EMIFD6: TEST_PH1.19 ; also on sheet 16
DSP_EMIFD7: TEST_PH1.21 ; also on sheet 16
DSP_EMIFD8: TEST_PH1.23 ; also on sheet 16
DSP_EMIFD9: TEST_PH1.25 ; also on sheet 16
DSP_EMIFD10: TEST_PH1.27 ; also on sheet 16
DSP_EMIFD11: TEST_PH1.29 ; also on sheet 16
DSP_EMIFD12: TEST_PH1.31 ; also on sheet 16
DSP_EMIFD13: TEST_PH1.33 ; also on sheet 16
DSP_EMIFD14: TEST_PH1.35 ; also on sheet 16
DSP_EMIFD15: TEST_PH1.37 ; also on sheet 16
DSP_EMIFOEZ: TEST_PH1.47 ; also on sheet 16
DSP_EMIFRNW: TEST_PH1.51 ; also on sheet 16
DSP_EMIFWAIT1: TEST_PH1.53 ; also on sheet 16
DSP_EMIFWEZ: TEST_PH1.49 ; also on sheet 16
DSP_GPIO_00: FPGA1.H1(IO_L11N_3/LHCLK1) ; also on sheet 4
DSP_GPIO_01: FPGA1.G2(IO_L11P_3/LHCLK0) ; also on sheet 4
DSP_GPIO_02: FPGA1.J3(IO_L12N_3/IRDY2/LHCLK3) ; also on sheet 4
DSP_GPIO_03: FPGA1.H3(IO_L12P_3/LHCLK2) ; also on sheet 4
DSP_GPIO_04: FPGA1.J1(IO_L14N_3/LHCLK5) ; also on sheet 4
DSP_GPIO_05: FPGA1.J2(IO_L14P_3/LHCLK4) ; also on sheet 4
DSP_GPIO_06: FPGA1.K1(IO_L15N_3/LHCLK7) ; also on sheet 4
DSP_GPIO_07: FPGA1.K3(IO_L15P_3/TRDY2/LHCLK6) ; also on sheet 4
DSP_GPIO_08: FPGA1.L2(IO_L16N_3) ; also on sheet 4
DSP_GPIO_09: FPGA1.L1(IO_L16P_3/VREF_3_2) ; also on sheet 4
DSP_GPIO_10: FPGA1.J6(IO_L17N_3) ; also on sheet 4
DSP_GPIO_11: FPGA1.J4(IO_L17P_3) ; also on sheet 4
DSP_GPIO_12: FPGA1.L3(IO_L18N_3) ; also on sheet 4
DSP_GPIO_13: FPGA1.K4(IO_L18P_3) ; also on sheet 4
DSP_GPIO_14: FPGA1.L4(IO_L19N_3) TEST_PH1.78 ; also on sheet 4
DSP_GPIO_15: FPGA1.M3(IO_L19P_3) TEST_PH1.80 ; also on sheet 4
DSP_McBSP0_FSR: TEST_PH1.56 ; also on sheet 13 29
DSP_McBSP0_FST: TEST_PH1.58 ; also on sheet 13 29
DSP_McBSP0_RX: TEST_PH1.60 ; also on sheet 12 13
DSP_McBSP0_RXCLK: R1177.1 ; also on sheet 13 29
DSP_McBSP0_SLCLK: R1183.1 ; also on sheet 13 29
DSP_McBSP0_TX: TEST_PH1.62 ; also on sheet 12 13
DSP_McBSP0_TXCLK: R1179.1 ; also on sheet 13 29
DSP_McBSP1_FSR: TEST_PH1.70 ; also on sheet 13 29
DSP_McBSP1_FST: TEST_PH1.72 ; also on sheet 13 29
DSP_McBSP1_RX: TEST_PH1.74 ; also on sheet 12 13
DSP_McBSP1_RXCLK: R1188.1 ; also on sheet 13 29
DSP_McBSP1_SLCLK: R1186.1 ; also on sheet 13 29
DSP_McBSP1_TX: TEST_PH1.76 ; also on sheet 12 13
DSP_McBSP1_TXCLK: R1189.1 ; also on sheet 13 29
DSP_SCL: TEST_PH1.5 ; also on sheet 4 12
DSP_SDA: TEST_PH1.3 ; also on sheet 4 12
DSP_SSPCS1: TEST_PH1.67 ; also on sheet 4 29
DSP_SSPMISO: R399.2 ; also on sheet 4 29
DSP_SSPMOSI: TEST_PH1.65 ; also on sheet 4 29
DSP_TIMI0: FPGA1.P2(IO_L23N_3) TEST_PH1.55 ; also on sheet 4
DSP_TIMI1: FPGA1.R1(IO_L23P_3) TEST_PH1.59 ; also on sheet 4
DSP_TIMO0: FPGA1.M4(IO_L24N_3) TEST_PH1.57 ; also on sheet 4
DSP_TIMO1: FPGA1.N3(IO_L24P_3) TEST_PH1.61 ; also on sheet 4
DSP_UART1_CTS: TEST_PH1.77 ; also on sheet 4
DSP_UART1_RTS: TEST_PH1.75 ; also on sheet 4
DSP_UART1_RX: TEST_PH1.73 ; also on sheet 4
DSP_UART1_TX: TEST_PH1.71 ; also on sheet 4
FPGA_DONE: R473.2 ; also on sheet 29
FPGA_INIT#: FPGA1.T12(IO_L17P_2/~{INIT}) R923.2 R924.1
FPGA_M0: FPGA1.P4(IO_L01N_2/M0) R191.2 R197.1
FPGA_M1: FPGA1.N4(IO_L01P_2/M1) R192.2 R198.1
FPGA_M2: FPGA1.R2(IO_L02P_2/M2) R193.2 R199.1
FPGA_SPI_CS#: FPGA1.P13(IO_L19N_2) R194.2 U26.1(~{CS})
FPGA_SPI_HD#: R189.1 U26.7(~{HOLD})
FPGA_SPI_SCK: R190.1 R396.2 U26.6(SCK)
FPGA_SPI_SI: FPGA1.N12(IO_L19P_2) U26.5(SI)
FPGA_SPI_SO: FPGA1.T14(IO_L20P_2/D0/DIN/MISO) R195.2 U26.2(SO)
FPGA_SPI_WP#: R196.2 U26.3(~{WP})
FPGA_VID_OE#: FPGA1.T2(IO_L02N_2/~{CSO}) ; also on sheet 28
FPGA_VS0: FPGA1.P5(IO_L04N_2/VS0) R422.2
FPGA_VS1: FPGA1.N6(IO_L04P_2/VS1) R421.2
FPGA_VS2: FPGA1.T3(IO_L03N_2/VS2) R423.2
HyperLink_RXFLCLK: Hyperlink1.A2(sideband0) ; also on sheet 13
HyperLink_RXFLDAT: Hyperlink1.D2(sideband6) ; also on sheet 13
HyperLink_RXN0: Hyperlink1.B5(Rxn0) ; also on sheet 13
HyperLink_RXN1: Hyperlink1.A5(Rxn1) ; also on sheet 13
HyperLink_RXN2: Hyperlink1.B8(Rxn2) ; also on sheet 13
HyperLink_RXN3: Hyperlink1.A7(Rxp3) ; also on sheet 13
HyperLink_RXP0: Hyperlink1.B4(Rxp0) ; also on sheet 13
HyperLink_RXP1: Hyperlink1.A4(Rxp1) ; also on sheet 13
HyperLink_RXP2: Hyperlink1.B7(Rxp2) ; also on sheet 13
HyperLink_RXP3: Hyperlink1.A8(Rxn3) ; also on sheet 13
HyperLink_RXPMCLK: Hyperlink1.D1(sideband5) ; also on sheet 13
HyperLink_RXPMDAT: Hyperlink1.B1(sideband3) ; also on sheet 13
HyperLink_TXFLCLK: Hyperlink1.A1(sideband7) ; also on sheet 13
HyperLink_TXFLDAT: Hyperlink1.B2(sideband1) ; also on sheet 13
HyperLink_TXN0: Hyperlink1.D5(Txn0) ; also on sheet 13
HyperLink_TXN1: Hyperlink1.D8(Txn2) ; also on sheet 13
HyperLink_TXN2: Hyperlink1.C8(Txn3) ; also on sheet 13
HyperLink_TXN3: Hyperlink1.C4(Txp1) ; also on sheet 13
HyperLink_TXP0: Hyperlink1.D4(Txp0) ; also on sheet 13
HyperLink_TXP1: Hyperlink1.D7(Txp2) ; also on sheet 13
HyperLink_TXP2: Hyperlink1.C7(Txp3) ; also on sheet 13
HyperLink_TXP3: Hyperlink1.C5(Txn1) ; also on sheet 13
HyperLink_TXPMCLK: Hyperlink1.C2(sideband2) ; also on sheet 13
HyperLink_TXPMDAT: Hyperlink1.C1(sideband4) ; also on sheet 13
MAIN_48MHZ_CLK_R: FPGA1.T9(IO_L12N_2/GCLK3) R178.2
MMC_BOOTCOMP: MMC1.28(P2.3/TA1.2) ; also on sheet 29
MMC_DETECT#: MMC1.32(P2.5) ; also on sheet 29
MMC_ENABLE_N: Q1.1(GATE) R11.1 R16.1 ; also on sheet 12
MMC_GA0: MMC1.18(P1.1/TA0.0) R13.2 R18.1 ; also on sheet 12
MMC_GA1: MMC1.19(P1.2/TA0.1) R14.2 R19.1 ; also on sheet 12
MMC_GA2: MMC1.20(P1.3/TA0.2) R15.2 R20.1 ; also on sheet 12
MMC_GAPU: MMC1.21(P1.4/TA0.3) R13.1 R14.1 R15.1
MMC_LED1: D1.2(CATHODE) MMC1.22(P1.5/TA0.4)
MMC_LED2: D2.2(CATHODE) MMC1.24(P1.7)
MMC_MISO: MMC1.57(P5.7/UCA1RXD/UCA1SOMI) R960.1
MMC_MOSI: MMC1.56(P5.6/UCA1TXD/UCA1SIMO) R961.1
MMC_P43: MMC1.43(P4.0/TB0.0) TP17.1
MMC_POR_AMC#: MMC1.27(P2.2/TA1.1) ; also on sheet 29
MMC_RSTSTAT#: MMC1.29(P2.4/RTCCLK) ; also on sheet 29
MMC_SBWTCK: MMC1.71(TEST/SBWTCK) SBW_MMC1.4
MMC_SBWTDIO: C371.2 MMC1.76(RST#/NMI/SBWTDIO) Q1.3(DRAIN) R10.2 SBW_MMC1.3
MMC_SCK: MMC1.41(P3.6/UCB1STE/UCA1CLK) R963.1
MMC_SPI_MISO: FPGA1.N10(IO_L13P_2) R960.2
MMC_SPI_MOSI: FPGA1.P10(IO_L14N_2/MOSI/~{CSI}) R961.2
MMC_SPI_SCK: FPGA1.R9(IO_L12P_2/GCLK2) R963.2
MMC_SPI_STE: FPGA1.M10(IO_L13N_2) R962.2
MMC_STE: MMC1.55(P5.5/UCB1CLK/UCA1STE) R962.1
MMC_WR_AMC#: MMC1.26(P2.1/TA1.0) ; also on sheet 29
MMC_XTAL1: C5.1 MMC1.13(P7.0/XIN) Y1.1
MMC_XTAL2: C8.1 MMC1.14(P7.1/XOUT) Y1.2
PCIESSEN: FPGA1.M1(IO_L20P_3) R408.1 SW9.1(A1)
PH_SSPCK: TEST_PH1.69 ; also on sheet 4
PHY_INT#: FPGA1.T6(IO_L06N_2/D6) ; also on sheet 19
PHY_RST: FPGA1.T5(IO_L06P_2/D7) ; also on sheet 19
REFCLK2_PD#: FPGA1.T7(IO_L09N_2/GCLK13) ; also on sheet 20
SMB_SCL_IPMBL: MMC1.37(P3.2/UCB0SOMI/UCB0SCL) R2.1 ; also on sheet 12
SMB_SDA_IPMBL: MMC1.36(P3.1/UCB0SIMO/UCB0SDA) R1.1 ; also on sheet 12
UART_FT_RX: R7.2 ; also on sheet 4 6
UART_FT_TX: R6.2 ; also on sheet 4 6
UCD9222_VID2A: FPGA1.T10(IO_L14P_2) ; also on sheet 27
UCD9222_VID2B: FPGA1.R11(IO_L15N_2/DOUT) ; also on sheet 27
UCD9222_VID2C: FPGA1.T11(IO_L15P_2/AWAKE) ; also on sheet 27
UCD9222_VID2S: FPGA1.N11(IO_L16N_2) ; also on sheet 27
User_define: FPGA1.P1(IO_L22N_3) R407.1 SW9.2(A2)
N70710337: D2.1(ANODE) R4.2
N70710373: D1.1(ANODE) R3.2
N70729864: C7.2 MMC1.49(VCORE)
N70762560: MMC1.40(P3.5/UCA0RXD/UCA0SOMI) R7.1
N70764137: MMC1.39(P3.4/UCA0TXD/UCA0SIMO) R6.1
N70767489: MMC1.33(P2.6/ACLK) TP8.1
N70767673: MMC1.25(P2.0/TA1CLK/MCLK) TP9.1
N70902929: B1.1 C6.2 MMC1.11(AVCC)
N71260391: MMC1.23(P1.6/SMCLK) TP7.1
N71269048: R399.1 TEST_PH1.63
N71269507: R1177.2 TEST_PH1.50
N71269509: R1179.2 TEST_PH1.52
N71322495: B36.1 C388.2 C435.2 C440.2 C530.2 FPGA1.M9(VCCO_2_1) FPGA1.R4(VCCO_2_2) FPGA1.R8(VCCO_2_3) FPGA1.R12(VCCO_2_4)
N71322551: R211.2 SW3.16
N71322574: FPGA1.L7(IP_2_1) R473.1
N71322676: B35.2 C389.2 C390.2 C436.2 C439.2 FPGA1.D2(VCCO_3_1) FPGA1.H2(VCCO_3_2) FPGA1.J5(VCCO_3_3) FPGA1.M2(VCCO_3_4)
N71322721: FPGA_D4.1(ANODE) R208.1
N71322771: R212.2 SW3.15
N71322778: R403.2 SW9.4(B1)
N71322780: R402.2 SW9.3(B2)
N71323102: R214.2 SW3.14
N71323273: FPGA_D2.1(ANODE) R206.1
N71323293: FPGA_D3.1(ANODE) R207.1
N71323306: FPGA_D1.1(ANODE) R205.1
N71323395: R216.2 SW3.13
N71323515: R310.2 SW5.12
N71323529: R311.2 SW5.11
N71323533: R307.2 SW5.10
N71323537: R313.2 SW5.9
N71324343: B24.1 C382.2 Y7.1(OE) Y7.4(VCC)
N71324377: R178.1 Y7.3(OUT)
N71324518: R285.2 SW3.12
N71324541: R289.2 SW3.11
N71324545: R283.2 SW3.10
N71324549: R297.2 SW3.9
N71325006: FPGA1.R14(IO_L20N_2/CCLK) R396.1
N71325031: FPGA1.N7(IO_L07P_2) R397.1
N71325054: R302.2 SW5.16
N71325071: R303.2 SW5.15
N71325075: R300.2 SW5.14
N71325079: R305.2 SW5.13
N79145976: R1183.2 TEST_PH1.54
N79146113: R1186.2 TEST_PH1.68
N79146175: R1188.2 TEST_PH1.64
N79146177: R1189.2 TEST_PH1.66

Not connected (* = marked no-connect by the designer): FPGA1 E4(IP_L04P_3)* F4(IP_L04N_3/VREF_3_3)* G5(IP_L06N_3/VREF_3_4)* G6(IP_L06P_3)* H7(IP_L13P_3)* J7(IP_L13N_3)* K5(IP_L21P_3)* K6(IP_L21N_3)* L5(IP_L25P_3)* L6(IP_L25N_3/VREF_3_5)* L8(IP_2_2)* L9(IP_2_3/VREF_2_1)* L10(IP_2_4/VREF_2_2)* M7(IP_2_5/VREF_2_3)* M8(IP_2_6/VREF_2_4)* M11(IP_2_7/VREF_2_5)* N1(IO_L20N_3)* N2(IO_L22P_3)* N5(IP_2_8/VREF_2_6)* N9(IO_L11P_2/GCLK0) P8(IO_L10P_2/GCLK14) P9(IO_L11N_2/GCLK1) R3(IO_L03P_2/~{RDWR})* R7(IO_L09P_2/GCLK12) T4(IO_L05P_2) T8(IO_L10N_2/GCLK15); Hyperlink1 H1(NPTH1) H2(NPTH2); MMC1 1(P6.4/A4)* 2(P6.5/A5)* 3(P6.6/A6)* 4(P6.7/A7)* 5(P7.4/A12)* 6(P7.5/A13)* 7(P7.6/A14)* 8(P7.7/A15)* 9(P5.0/A8/VREF+/VEREF+)* 10(P5.1/A9/VREF-/VEREF-)* 17(P1.0/TA0CLK/ACLK)* 34(P2.7/ADC12CLK/DMAE0)* 35(P3.0/UCB0STE/UCA0CLK)* 38(P3.3/UCB0CLK/UCA0STE)* 42(P3.7/UCB1SIMO/UCB1SDA)* 44(P4.1/TB0.1)* 45(P4.2/TB0.2)* 46(P4.3/TB0.3)* 47(P4.4/TB0.4)* 48(P4.5/TB0.5)* 52(P4.6/TB0.6)* 53(P4.7/TB0CLK/SMCLK)* 54(P5.4/UCB1SOMI/UCB1SCL)* 58(P7.2/TB0OUTH/SVMOUT)* 59(P7.3/TA1.2)* 60(P8.0/TA0.0)* 61(P8.1/TA0.1)* 62(P8.2/TA0.2)* 63(P8.3/TA0.3)* 64(P8.4/TA0.4)* 65(P8.5/TA1.0)* 66(P8.6/TA1.1)* 69(P5.2/XT2IN)* 70(P5.3/XT2OUT)* 72(PJ.0/TDO)* 73(PJ.1/TDI/TCLK)* 74(PJ.2/TMS)* 75(PJ.3/TCK)* 77(P6.0/A0)* 78(P6.1/A1)* 79(P6.2/A2)* 80(P6.3/A3)*; TEST_PH1 H1(NPTH_1) H2(NPTH_2)

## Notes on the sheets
sheet 23
- IPASS+HD for HyperLink
- MMC INTERFACE
- MSP430 Power
- SpyBiWire
- DEBUG HEADER
- The NU resistors on these connections to the
  MSP430 are for debug use only and will be
  used only with the shunts removed from pins
  1 and 2 of CN7
- SPI Interface for
  FPGA debugging.
- (Red LED)
- (Blue LED)
sheet 24
- FPGA INTERFACE CONTROL DIAGRAM
sheet 25
- POWER DISTRIBUTION
sheet 26
- BOOT STRAP CONFIGURATION
- FPGA, BOOT MODE & SMART REFLEX
- Boot Configuration
- DIP Switch
- DSP
- BM_GPIO
- Primary Function
- VID  Enable
- 0 - Big Endian
  1 - Little Endian
- BM_GPIO0
- GPIO0
- ENDIANESS
- BOOT MODE
  SWITCH
- BM_GPIO[4:1]
- GPIO[4:1]
- BOOTMODE[3:0]
- Boot Device
- BM_GPIO[10:5]
- GPIO[10:5]
- BOOTMODE[9:4]
- Boot Device Config
- BM_GPIO[13:11]
- GPIO[13:11]
- BOOTMODE[12:10]
- PLL Multiplier/I2C
- PHY 88E1112
- BM_GPIO[15:14]
- GPIO[15:14]
- PCIESSMODE[1:0]
- Endpt/RootComplex
- CLOCK GEN
- Boot Device
- BM_GPIO
- BM_GPIO
- DSP GPIO
  TO FPGA
- Boot Device
- Boot Device
- [4:1]
- [4:1]
- MMC SPI
- 0 0 0 0
- Sleep/EMIF16
- X 1 0 1
- I2C Master
- 0 0 0 1
- SRIO
- 0 1 0 1
- I2C Slave
- UCD9222 VID CTRL
- X 0 1 0
- Ethernet
- X 1 1 0
- SPI
- Reserved for future use
- 0 0 1 1
- NAND
- 0 1 1 1
- Hyperlink
- 0 1 0 0
- PCIe
- 1 0 0 0
- UART
- Note: GPIO[10:5] bit definitions depend on the boot
  mode.
- FPGA EEPROM
- Boot PLL Settings
- BM_GPIO
- Input Clock
- BM_GPIO
- Input Clock
- For FPGA internal reset.
- [13:11]
- (in MHz)
- [13:11]
- (in MHz)
- 0 0 0
- 50.00
- 1 0 0
- 156.25
- 0 0 1
- 66.67
- 1 0 1
- 250.00
- 0 1 0
- 80.00
- 1 1 0
- 312.50
- 0 1 1
- 100.00
- 1 1 1
- 122.88
- PCIe Mode Selection PCIESSMODE[1:0]
- BM_GPIO
- PCIe Mode
- [15:14]
- 0 0
- End-point mode
- 0 1
- Legacy End-point mode (support for legacy INTx)
- 1 0
- Root complex mode
- 1 1
- Reserved
- PCIESSEN
- BM_GPIO16
- PCIe Status
- DEBUG_LED
- 0
- PCIe module disabled
- 1
- PCIe module enabled
